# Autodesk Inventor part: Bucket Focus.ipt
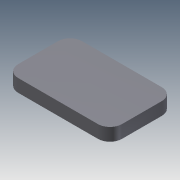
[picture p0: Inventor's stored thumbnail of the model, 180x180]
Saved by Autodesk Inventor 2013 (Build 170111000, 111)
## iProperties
Created: 2005-04
Part Number: Bucket Focus.ipt
Material: Steel, Mild
Document SubType Name: Modeling
Designer: salex
Manufacturer: Standard
Standards Organization: Custom
Density: 7.86 g/cm^3
Author: salex
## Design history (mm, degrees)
sketch "Эскиз1"
  geometry: L1 (-303.58, 170)-(-50.548, 170) reference; L2 (-303.58, 210)-(-50.548, 210) reference; L3 (0, 1420)-(-250, 1420) reference; L4 (-250, 0)-(-250, 1420) reference; L5 (0, 0)-(-250, 0) reference; L6 (0, 0)-(0, 1420) reference; L7 (-130, 230)-(-30, 230); L8 (-15, 215)-(-15, 165); L9 (-30, 150)-(-130, 150); L10 (-145, 165)-(-145, 215); A1 r 15 centre (-30, 215) between (-15, 215) and (-30, 230); A2 r 15 centre (-30, 165) between (-30, 150) and (-15, 165); A3 r 15 centre (-130, 165) between (-145, 165) and (-130, 150); A4 r 15 centre (-130, 215) between (-130, 230) and (-145, 215)
  constraints: 8 end point, 8 point on circle, 8 tangent, 4 centre point, 3 equal radius, 2 parallel, 1 horizontal, 1 perpendicular
  dimensions: "d0" = 15 radius of A1; "d1" = 20 distance between parallel lines of L2 L7; "d2" = 20 distance between parallel lines of L9 L1 (= d1); "d3" = 15 distance between parallel lines of L8 L6; "d4" = 130 distance between parallel lines of L8 L10
extrude "Выдавливание1" new body sketch "Эскиз1" distance "d5" = 16; taper "d6" = 0 deg
body "Solid1"
node "ЗаимстЛин1"
node "ЗаимстЛин2"
node "ЗаимстЛин3"
